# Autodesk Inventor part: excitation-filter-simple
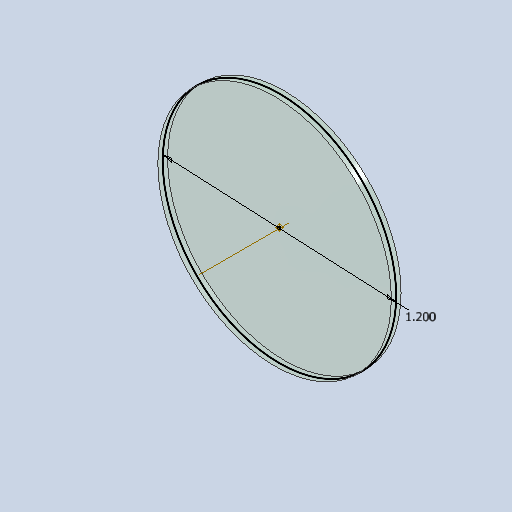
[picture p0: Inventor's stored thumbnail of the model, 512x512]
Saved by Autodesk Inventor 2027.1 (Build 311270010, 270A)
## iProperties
Created: 2026-08
Part Number: excitation-filter-simple
Material: Generic
Document SubType Name: Modeling
Designer: dunge
Density: 1 g/cm^3
Appearance: Default
Author: dunge
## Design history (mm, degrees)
sketch "Sketch1"
  geometry: C1 r 15.24 at (0, 0); 1 further point
  constraints: 1 centre point, 1 coincident
  dimensions: "d0" = 30.48 diameter of C1
extrude "Extrusion1" new body sketch "Sketch1" stored distance "d1" = 1.27; taper "d2" = 0 deg
workpoint "Work Point1"
workaxis "Work Axis1"
body "Solid1"
node "Finishes"
node "Finish1" dims "Finish1_Area" = 158.09273
